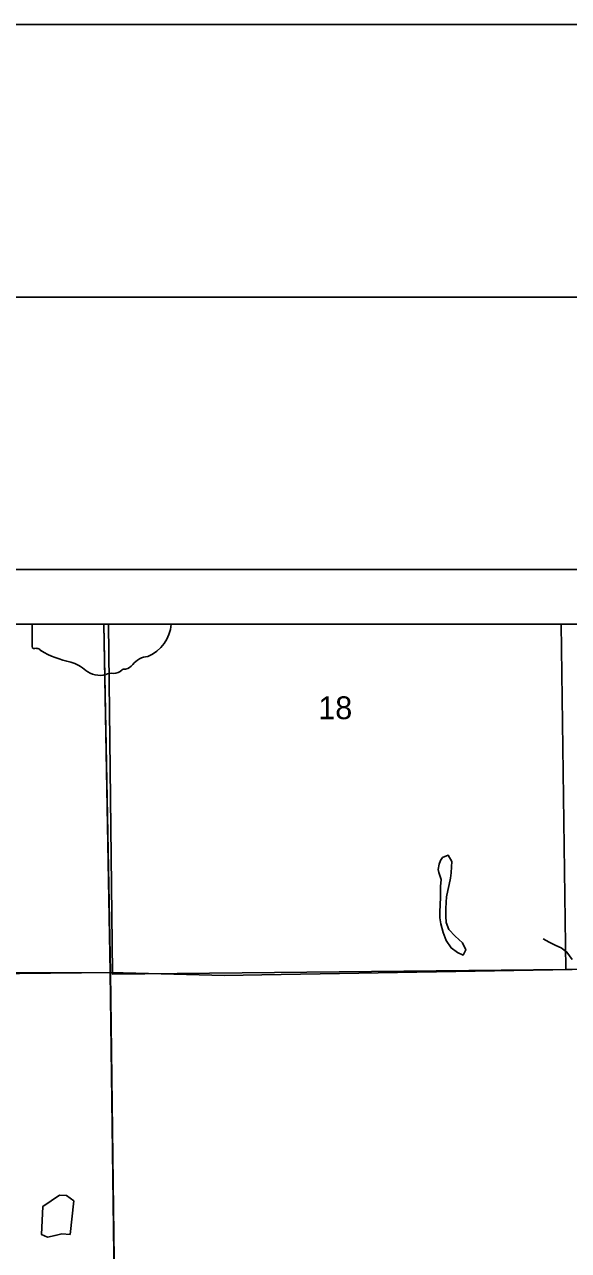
# Model space of a CAD drawing. Extents: x 0 to 34, y 0 to 22.
# Drawn here: x 5.353 to 6.351, y 19.751 to 22 of the extents above; entities that cross this region are included whole.
import ezdxf

# ---------------------------------------------------------------- set-up
doc = ezdxf.new("R2010")
doc.units = 0
for name, color, linetype in [('GM_X_Major_River_Text', 7, 'Continuous'), ('GM_X_Minor_Lake', 7, 'Continuous'), ('GM_X_Minor_River', 7, 'Continuous'), ('GM_X_Rail_Line', 7, 'Continuous'), ('GM_X_Section_Text', 7, 'Continuous'), ('GM_X_State_Route', 7, 'Continuous'), ('GM_X_State_Shield', 7, 'Continuous'), ('SH_Border', 7, 'Continuous'), ('SH_Cut_Line', 7, 'Continuous'), ('SH_Data', 7, 'Continuous')]:
    doc.layers.add(name, color=color, linetype=linetype)

msp = doc.modelspace()

# ---------------------------------------------------------------- linework, layer by layer
at = {"layer": 'GM_X_Major_River_Text'}
msp.add_lwpolyline([(5.622, 20.9), (5.3669, 20.9), (5.3669, 20.8586)], dxfattribs=at)
for centre, radius, start, end in [((5.5523, 20.9053), 0.0699, 292.3089, 355.6847), ((5.3699, 20.8581), 0.00308, 171.4911, 258.3065), ((5.3704, 20.8786), 0.0235, 267.339, 280.6039), ((5.3752, 20.847), 0.00848, 29.7484, 93.2717), ((5.4823, 21.0268), 0.2019, 240.4129, 257.1985), ((5.4221, 20.7686), 0.0632, 47.1842, 75.836), ((5.5818, 20.8024), 0.0383, 94.4031, 142.5768), ((5.4904, 20.846), 0.0401, 230.7004, 286.2918), ((5.5136, 20.7768), 0.0329, 85.6951, 111.21), ((5.5165, 20.831), 0.0214, 268.777, 315.5493), ((5.5358, 20.8116), 0.00601, 65.7517, 132.6484), ((5.5333, 20.8392), 0.0226, 282.8732, 323.2771)]:
    msp.add_arc(centre, radius, start, end, dxfattribs=at)
at = {"layer": 'GM_X_Minor_Lake'}
for points in [[(6.1198, 20.4715), (6.1157, 20.4661), (6.1135, 20.4592), (6.1116, 20.4499), (6.1126, 20.4444)], [(6.1126, 20.4444), (6.117, 20.4312), (6.1161, 20.4186), (6.1157, 20.3988), (6.1151, 20.3848), (6.115, 20.3722), (6.1148, 20.3612), (6.1165, 20.3499), (6.1209, 20.3344), (6.1261, 20.3192), (6.1354, 20.3057), (6.1473, 20.2972), (6.1573, 20.2928), (6.1624, 20.3024), (6.1561, 20.3152), (6.1427, 20.3275), (6.1311, 20.3398), (6.1263, 20.3527), (6.1257, 20.3644), (6.1259, 20.3774), (6.1261, 20.3899), (6.127, 20.3994), (6.1295, 20.4109), (6.132, 20.4219), (6.1341, 20.4337), (6.1354, 20.4436), (6.136, 20.4546), (6.1366, 20.4642), (6.1303, 20.4758), (6.1198, 20.4715)], [(5.4431, 19.8419), (5.4297, 19.8519), (5.4168, 19.8521), (5.4018, 19.8416), (5.3867, 19.8315), (5.3838, 19.7801), (5.3949, 19.775), (5.4089, 19.7783), (5.4214, 19.7811), (5.4366, 19.7799)], [(5.4366, 19.7799), (5.4431, 19.8419)]]:
    msp.add_lwpolyline(points, dxfattribs=at)
at = {"layer": 'GM_X_Minor_River'}
msp.add_lwpolyline([(6.3575, 20.2843), (6.3478, 20.2982), (6.3374, 20.306), (6.3274, 20.31), (6.3156, 20.3166), (6.3041, 20.3225)], dxfattribs=at)
at = {"layer": 'GM_X_Rail_Line'}
for points in [[(5.523, 19.2739), (5.5102, 20.2613), (5.4984, 20.9), (2.1, 20.9)], [(8.9, 20.9), (5.4984, 20.9), (5.5102, 20.2613), (5.523, 19.2739)]]:
    msp.add_lwpolyline(points, dxfattribs=at)
at = {"layer": 'GM_X_State_Route'}
for p, q in [((5.5104, 20.2608), (5.4986, 20.9)), ((5.516, 19.828), (5.5104, 20.2608))]:
    msp.add_line(p, q, dxfattribs=at)
for points in [[(5.7884, 20.2566), (6.3932, 20.267), (6.3942, 20.267)], [(4.0013, 20.2492), (4.6171, 20.2548), (4.9829, 20.2595), (5.5104, 20.2608)], [(5.5104, 20.2608), (5.7199, 20.2554), (5.7884, 20.2566)], [(5.5233, 19.2646), (5.5232, 19.2733), (5.516, 19.828)]]:
    msp.add_lwpolyline(points, dxfattribs=at)
at = {"layer": 'GM_X_State_Shield'}
for points in [[(5.5067, 20.9), (4.4883, 20.9), (4.4904, 20.2497), (5.514, 20.2608)], [(6.3373, 20.9), (5.5067, 20.9), (5.514, 20.2608), (5.514, 20.2578), (6.3461, 20.2662)], [(7.3363, 20.9), (6.3373, 20.9), (6.3461, 20.2662), (7.3448, 20.2776)]]:
    msp.add_lwpolyline(points, close=True, dxfattribs=at)
at = {"layer": 'SH_Border'}
msp.add_lwpolyline([(1.5, 21.5), (33.5, 21.5), (33.5, 0.5), (1.5, 0.5)], close=True, dxfattribs=at)
at = {"layer": 'SH_Cut_Line'}
msp.add_lwpolyline([(0, 0), (34, 0), (34, 22), (0, 22)], close=True, dxfattribs=at)
msp.add_lwpolyline([(8.9, 20.9), (2.1, 20.9)], dxfattribs=at)
at = {"layer": 'SH_Data'}
for p, q in [((2, 21), (9, 21)), ((2.1, 20.9), (8.9, 20.9))]:
    msp.add_line(p, q, dxfattribs=at)

# ---------------------------------------------------------------- texts
at = {"layer": 'GM_X_Section_Text'}
msp.add_text('18', height=0.04186, rotation=0, dxfattribs=at).set_placement((5.8918, 20.7255))

doc.saveas('drawing.dxf')
